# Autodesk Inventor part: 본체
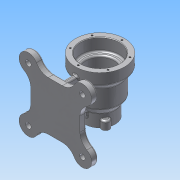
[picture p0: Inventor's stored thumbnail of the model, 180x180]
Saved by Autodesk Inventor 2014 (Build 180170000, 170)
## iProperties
Created: 2017-03
Part Number: 본체
Material: 알루미늄 6061
Document SubType Name: Modeling
Designer: 703
Density: 2.71 g/cm^3
Appearance: 알루미늄 - 평지
Mass: 1000.76 g
Surface Area: 838.864 cm^2
Volume: 369.286 cm^3
Author: 703
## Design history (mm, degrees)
sketch "스케치2" dims "d3" = 140
  geometry: L1 (45, -45)-(-45, -45); L2 (-45, -45)-(-45, 45); L3 (-45, 45)-(45, 45); L4 (45, 45)-(45, -45); L5 (45, -45)-(-45, 45); L6 (-45, -45)-(45, 45); L7 (0, 0)-(49.497, -49.497); L8 (0, 0)-(0, 21.069); L9 (0, 0)-(-23.484, 0); L10 (-49.497, -66.497)-(-49.497, -32.497); C1 r 17 at (49.497, -49.497); C2 r 17 at (-49.497, 49.497); C3 r 17 at (49.497, 49.497); A1 r 17 centre (-49.497, -49.497) between (-49.497, -66.497) and (-49.497, -32.497); 1 further point
  constraints: 20 end point, 4 centre point, 3 parallel, 3 perpendicular, 3 symmetric about line, 2 coincident, 2 midpoint, 2 point on circle, 1 horizontal, 1 point on line, 6 other
  dimensions: "d1" = 90 distance between parallel lines of L4 L2; "d2" = 90 distance between parallel lines of L3 L1; "d4" = 34 diameter of C1; "d116" = 34 distance of L10.start L10.end
extrude "돌출1" new body sketch "스케치2" distance "d5" = 12; taper "d6" = 0 deg
fillet "모깎기1" dims "d7" = 25
sketch "스케치3"
  geometry: L1 (-12.842, -45)-(12.842, -45) reference; L2 (0, 0)-(-25, 0); L3 (0, 0)-(25, 0); L4 (-25, 4)-(25, 4); L5 (25, 4)-(25, -4); L6 (25, -4)-(-25, -4); L7 (-25, -4)-(-25, 4); L8 (-25, 4)-(25, -4); L9 (25, 4)-(-25, -4); L10 (0, 0)-(0, 37); L11 (-4, -37)-(4, -37); L12 (4, 37)-(-4, 37); L13 (-4, 37)-(-4, -37); L14 (-4, -37)-(4, 37); L15 (4, -37)-(-4, 37); L16 (4, 37)-(4, 0); L17 (4, 0)-(4, -37)
  constraints: 32 end point, 5 parallel, 4 midpoint, 2 horizontal, 2 perpendicular, 1 collinear, 1 point on line
  dimensions: "d8" = 25 distance of L2.start L2.end; "d9" = 25 distance of L2.start L3.end; "d10" = 8 distance between parallel lines of L6 L4; "d11" = 50 distance between parallel lines of L7 L5; "d14" = 74 distance between parallel lines of L11 L12; "d113" = 37 distance of L12.start L16.end; "d114" = 8 distance between parallel lines of L13 L16; "d115" = 37 distance between parallel lines of L11 L3 (derived)
extrude "돌출2" join sketch "스케치3" distance "d15" = 73; taper "d16" = 0 deg
sketch "스케치4"
  geometry: L1 (0, 73)-(21, 73) reference; L2 (0, 0)-(0, 73) reference; L3 (0, 0)-(12.872, 73); L4 (-9.661, 0)-(-41.497, 0) reference; L5 (12.872, 73)-(0, 73); L6 (0, 0)-(0, 73); 2 further points
  constraints: 6 end point, 1 collinear, 1 parallel, 1 point on line
  dimensions: "d17" = 100 deg angle of L4 L3
extrude "돌출3" cut sketch "스케치4" stored distance "d18" = 73; taper "d19" = 0 deg
node "작업 평면1"
sketch "스케치5"
  geometry: L1 (0, 0)-(0, 82); C1 r 45 at (0, 82)
  constraints: 2 end point, 1 centre point, 1 coincident, 1 vertical
  dimensions: "d21" = 82 distance of L1.start L1.end; "d23" = 90 diameter of C1
extrude "돌출4" join sketch "스케치5" distance "d24" = 20; taper "d25" = 0 deg
sketch "스케치6"
  geometry: L1 (37.178, 30)-(127, 30) reference; L2 (37, 50)-(127, 50) reference; L3 (37.178, 37)-(37.178, 30) reference; L4 (37.178, 37)-(37.178, 37) reference; L5 (37.178, 30)-(37.178, 30) reference; L6 (82, 50)-(82, 19); L7 (82, 19)-(118, 19); L8 (118, 19)-(127, 30); L9 (82, 30)-(127, 30); L10 (37.178, 30)-(37.178, 37) reference; 1 further point
  constraints: 8 end point, 2 point on line, 1 midpoint, 1 parallel, 1 perpendicular
  dimensions: "d26" = 31 distance of L6.start L6.end; "d27" = 36 distance of L6.end L7.end
revolve "회전1" sketch "스케치6" stored, may be unused: angle "d28" = 90 deg
sketch "스케치7"
  geometry: L1 (-4, 3)-(-4, -35.777) reference; L2 (4, 3)-(-4, 3) reference; L3 (4, -35.777)-(4, 3) reference; C1 r 36 at (0, 0); A1 r 36 centre (0, 0) between (4, -35.777) and (-4, -35.777) reference; 1 further point
  constraints: 1 centre point, 1 coincident
  dimensions: "d29" = 72 diameter of C1
extrude "돌출5" join sketch "스케치7" distance "d30" = 34; taper "d31" = 0 deg
sketch "스케치8"
  geometry: L1 (37, 50)-(127, 50) reference; L2 (82, 50)-(82, -15); L3 (82, -15)-(82, -27); L4 (82, -27)-(109.5, -27); L5 (46.223, -15)-(118, -15) reference; L6 (118, 19)-(118, -15) reference; L7 (109.5, -27)-(118, -15); L8 (82, -15)-(118, -15); 1 further point
  constraints: 10 end point, 2 perpendicular, 1 collinear, 1 midpoint
  dimensions: "d32" = 65 distance of L2.start L2.end; "d33" = 12 distance of L2.end L3.end; "d34" = 27.5 distance of L3.end L4.end
revolve "회전2" sketch "스케치8" stored, may be unused: angle "d35" = 90 deg
sketch "스케치9"
  geometry: C1 r 27.5 at (0, 0); A1 r 27.5 centre (0, 0) between (4, -27.208) and (-4, -27.208) reference; 1 further point
  constraints: 1 centre point, 1 coincident
  dimensions: "d36" = 55 diameter of C1
extrude "돌출6" join sketch "스케치9" distance "d37" = 23; taper "d38" = 0 deg
sketch "스케치10"
  geometry: C1 r 45 at (0, 0) reference; C2 r 35 at (0, 0); 1 further point
  constraints: 1 centre point, 1 coincident
  dimensions: "d39" = 70 diameter of C2
extrude "돌출7" cut sketch "스케치10" distance "d40" = 23; taper "d41" = 0 deg
sketch "스케치11"
  geometry: C1 r 35 at (0, 0) reference; C2 r 26 at (0, 0); 1 further point
  constraints: 1 centre point, 1 coincident
  dimensions: "d42" = 52 diameter of C2
extrude "돌출8" cut sketch "스케치11" distance "d43" = 47; taper "d44" = 0 deg
sketch "스케치12"
  geometry: C1 r 26 at (0, 0) reference; C2 r 17.5 at (0, 0); 1 further point
  constraints: 1 centre point, 1 coincident
  dimensions: "d45" = 35 diameter of C2
extrude "돌출9" cut sketch "스케치12" distance "d46" = 30; taper "d47" = 0 deg
sketch "스케치13"
  geometry: L1 (0, 0)-(0, 27.5); C1 r 7 at (0, 27.5); 1 further point
  constraints: 2 end point, 1 centre point, 1 coincident, 1 vertical, 1 vertical alignment, 1 other
  dimensions: "d48" = 14 diameter of C1
extrude "돌출10" join sketch "스케치13" distance "d49" = 15; taper "d50" = 0 deg
sketch "스케치15"
  geometry: A1 r 7 centre (0, 27.5) between (6.943, 26.609) and (-6.943, 26.609) reference; 1 further point
hole "구멍1" sketch "스케치15" at (0, 27.5) diameter "d54" = 3.242; stored, may be unused: countersink angle "d58" = 90 deg, drill point angle "d60" = 118 deg; dims "d55" = 9, "d56" = 4, "d57" = 2, "d59" = 11
sketch "스케치16" dims "d64" = 80
  geometry: L1 (0, 0)-(0, 40); C1 r 45 at (0, 0) reference; 1 further point
  constraints: 2 end point, 1 coincident, 1 vertical, 1 vertical alignment, 2 other
hole "구멍2" sketch "스케치16" at (0, 40) diameter "d65" = 3.242; stored, may be unused: countersink angle "d69" = 90 deg, drill point angle "d71" = 118 deg; dims "d66" = 9, "d67" = 4, "d68" = 2, "d70" = 11
sketch "스케치17"
  geometry: A1 r 17 centre (-49.497, 49.497) between (-34.661, 57.796) and (-57.796, 34.661) reference; 1 further point
hole "구멍3" sketch "스케치17" at (-49.497, 49.497) diameter "d75" = 10; stored, may be unused: countersink angle "d79" = 90 deg, drill point angle "d81" = 118 deg; dims "d76" = 9, "d77" = 4, "d78" = 2, "d80" = 11
chamfer "모따기1" distance "d82" = 1; stored, may be unused: second distance "d83" = 2, angle "d84" = 45 deg
fillet "모깎기2" dims "d85" = 3
fillet "모깎기3" dims "d86" = 3
fillet "모깎기4" dims "d87" = 1
fillet "모깎기5" dims "d91" = 3
fillet "모깎기6" dims "d92" = 3
fillet "모깎기7" dims "d93" = 3
fillet "모깎기8" dims "d94" = 3
node "작업 평면2"
sketch "스케치18"
  geometry: C1 r 5 at (0, -19); 1 further point
  constraints: 1 centre point, 1 coincident
  dimensions: "d95" = 10 diameter of C1
extrude "돌출11" join sketch "스케치18" distance "d97" = 4; taper "d99" = 0 deg; dims "d98" = 1, "d100" = 0
fillet "모깎기9" dims "d101" = 3
sketch "스케치20"
  geometry: C1 r 5 at (0, 0) reference
hole "구멍4" sketch "스케치20" at (0, 0) diameter "d102" = 4.134; stored, may be unused: countersink angle "d106" = 90 deg, drill point angle "d108" = 118 deg; dims "d103" = 9, "d104" = 4, "d105" = 2, "d107" = 21.75
sketch "스케치21"
  geometry: L1 (12.842, 45)-(-12.842, 45) reference; 2 further points
  constraints: 1 other
  dimensions: "d109" = 35 distance of point (35, 0) point (0, 0); "d110" = 45 distance from line of L1 point (35, 0)
extrude "돌출12" join sketch "스케치21" distance "d111" = 0.5; taper "d112" = 0 deg
node "솔리드1"
mirror "대칭1"
pattern_circular "원형 패턴1" dims angle "d52" = 360 deg
pattern_circular "원형 패턴2" dims angle "d62" = 360 deg
pattern_circular "원형 패턴3" dims angle "d73" = 360 deg
mirror "대칭2"
mirror "대칭3"
pattern_circular "원형 패턴4" dims angle "d89" = 360 deg
node "투영된 루프1"
